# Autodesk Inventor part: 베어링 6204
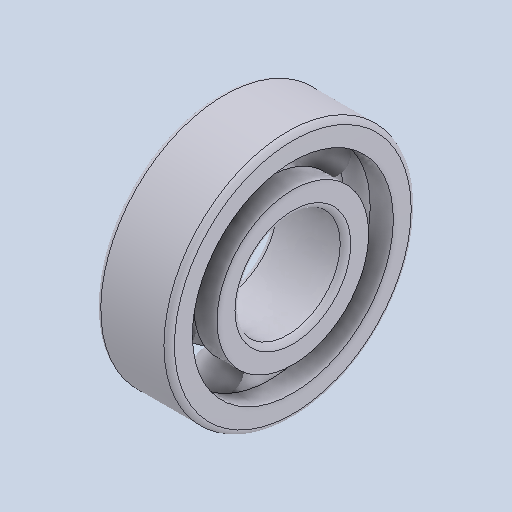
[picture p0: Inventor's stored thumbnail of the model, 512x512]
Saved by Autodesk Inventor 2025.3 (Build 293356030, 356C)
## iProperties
Created: 2025-08
Part Number: 베어링 6204
Material: 강철, 연강
Description: 깊은 그루브 볼 베어링
Document SubType Name: Modeling
Designer: user
Density: 7.86 g/cm^3
Appearance: 기본값
Author: jhkim
Sending System: Autodesk Inventor 2026
Preprocessor: ST-DEVELOPER v20.1
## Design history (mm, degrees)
sketch "스케치1"
  geometry: 1 further point
feature "Solid1"
feature "Solid1:1"
feature "Solid1:2"
feature "Solid1:3"
feature "Solid1:4"
feature "Solid1:5"
feature "Solid1:6"
feature "Solid1:7"
feature "Solid1:8"
node "솔리드1"
node "솔리드2"
node "솔리드3"
node "솔리드4"
node "솔리드5"
node "솔리드6"
node "솔리드7"
node "솔리드8"
node "솔리드9"
